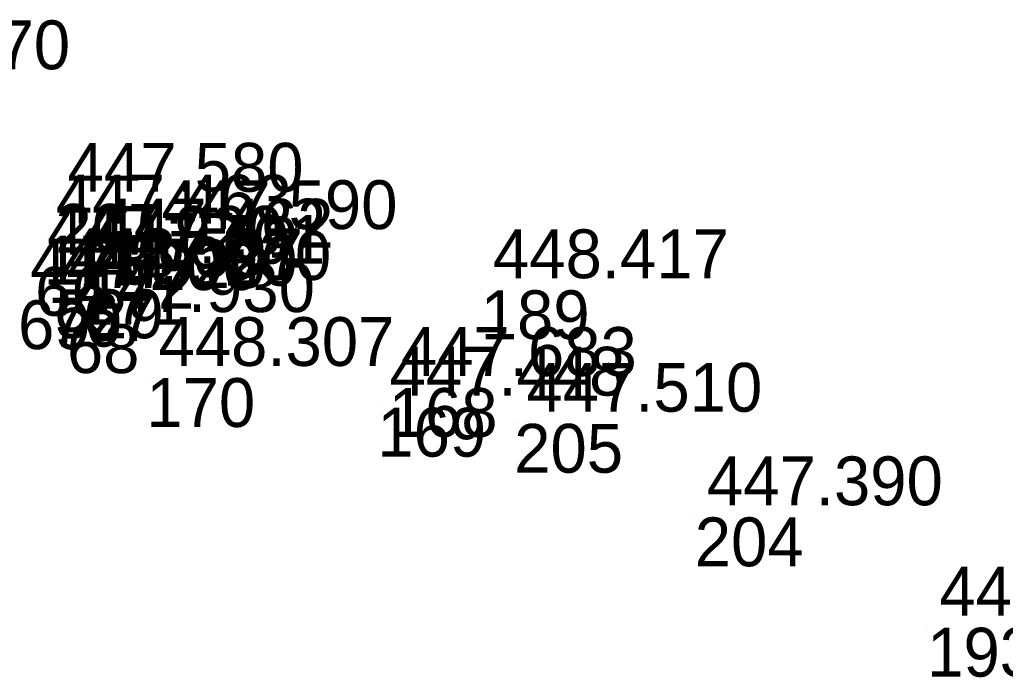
# Model space of a CAD drawing. Extents: x -874038 to -859694, y -1059487 to -1049069.
# Drawn here: x -862669.15 to -862644.91, y -1055380.14 to -1055363.97 of the extents above; entities that cross this region are included whole.
import ezdxf

# ---------------------------------------------------------------- set-up
doc = ezdxf.new("R2010")
doc.units = 0
doc.layers.add('Vrstva 60', color=7, linetype='Continuous')
doc.layers.add('Vrstva 61', color=7, linetype='Continuous')

msp = doc.modelspace()

# ---------------------------------------------------------------- linework, layer by layer
at = {"layer": 'Vrstva 60'}
for p, q in [((-862668.27, -1055368.5), (-862668.27, -1055368.5)), ((-862668.559, -1055369.284), (-862668.559, -1055369.284)), ((-862665.96, -1055369.42), (-862665.96, -1055369.42)), ((-862667.533, -1055369.876), (-862667.533, -1055369.876)), ((-862668.77, -1055370.05), (-862668.77, -1055370.05)), ((-862667.735, -1055370.273), (-862667.735, -1055370.273)), ((-862668.285, -1055370.604), (-862668.285, -1055370.604)), ((-862667.59, -1055370.67), (-862667.59, -1055370.67)), ((-862657.812, -1055370.627), (-862657.812, -1055370.627)), ((-862668.42, -1055370.81), (-862668.42, -1055370.81)), ((-862667.99, -1055371.46), (-862667.99, -1055371.46)), ((-862666.036, -1055372.785), (-862666.036, -1055372.785)), ((-862660.076, -1055373.029), (-862660.076, -1055373.029)), ((-862660.356, -1055373.514), (-862660.356, -1055373.514)), ((-862656.99, -1055373.91), (-862656.99, -1055373.91)), ((-862652.55, -1055376.21), (-862652.55, -1055376.21)), ((-862646.835, -1055378.923), (-862646.835, -1055378.923)), ((-862644.975, -1055378.777), (-862644.975, -1055378.777))]:
    msp.add_line(p, q, dxfattribs=at)

# ---------------------------------------------------------------- texts
for s, p in [('207', (-862668.27, -1055369.7)), ('173', (-862668.559, -1055370.484)), ('206', (-862665.96, -1055370.62)), ('172', (-862667.533, -1055371.076)), ('66', (-862668.77, -1055371.25)), ('171', (-862667.735, -1055371.473)), ('529', (-862668.285, -1055371.804)), ('67', (-862667.59, -1055371.87)), ('189', (-862657.812, -1055371.827)), ('69', (-862669.19, -1055372.07)), ('70', (-862668.42, -1055372.01)), ('68', (-862667.99, -1055372.66)), ('170', (-862666.036, -1055373.985)), ('168', (-862660.076, -1055374.229)), ('169', (-862660.356, -1055374.714)), ('205', (-862656.99, -1055375.11)), ('204', (-862652.55, -1055377.41)), ('193', (-862646.835, -1055380.123))]:
    msp.add_text(s, height=1.2, dxfattribs=at).set_placement(p)
at = {"layer": 'Vrstva 61'}
for s, p in [('447.470', (-862673.71, -1055365.19)), ('447.580', (-862667.97, -1055368.2)), ('447.463', (-862668.259, -1055368.984)), ('447.590', (-862665.66, -1055369.12)), ('447.462', (-862667.233, -1055369.576)), ('447.920', (-862668.47, -1055369.75)), ('447.701', (-862667.435, -1055369.973)), ('448.597', (-862667.985, -1055370.304)), ('447.930', (-862667.29, -1055370.37)), ('448.417', (-862657.512, -1055370.327)), ('447.920', (-862668.89, -1055370.57)), ('447.920', (-862668.12, -1055370.51)), ('447.930', (-862667.69, -1055371.16)), ('448.307', (-862665.736, -1055372.485)), ('447.683', (-862659.776, -1055372.729)), ('447.448', (-862660.056, -1055373.214)), ('447.510', (-862656.69, -1055373.61)), ('447.390', (-862652.25, -1055375.91)), ('447.505', (-862646.535, -1055378.623))]:
    msp.add_text(s, height=1.2, dxfattribs=at).set_placement(p)

doc.saveas('drawing.dxf')
